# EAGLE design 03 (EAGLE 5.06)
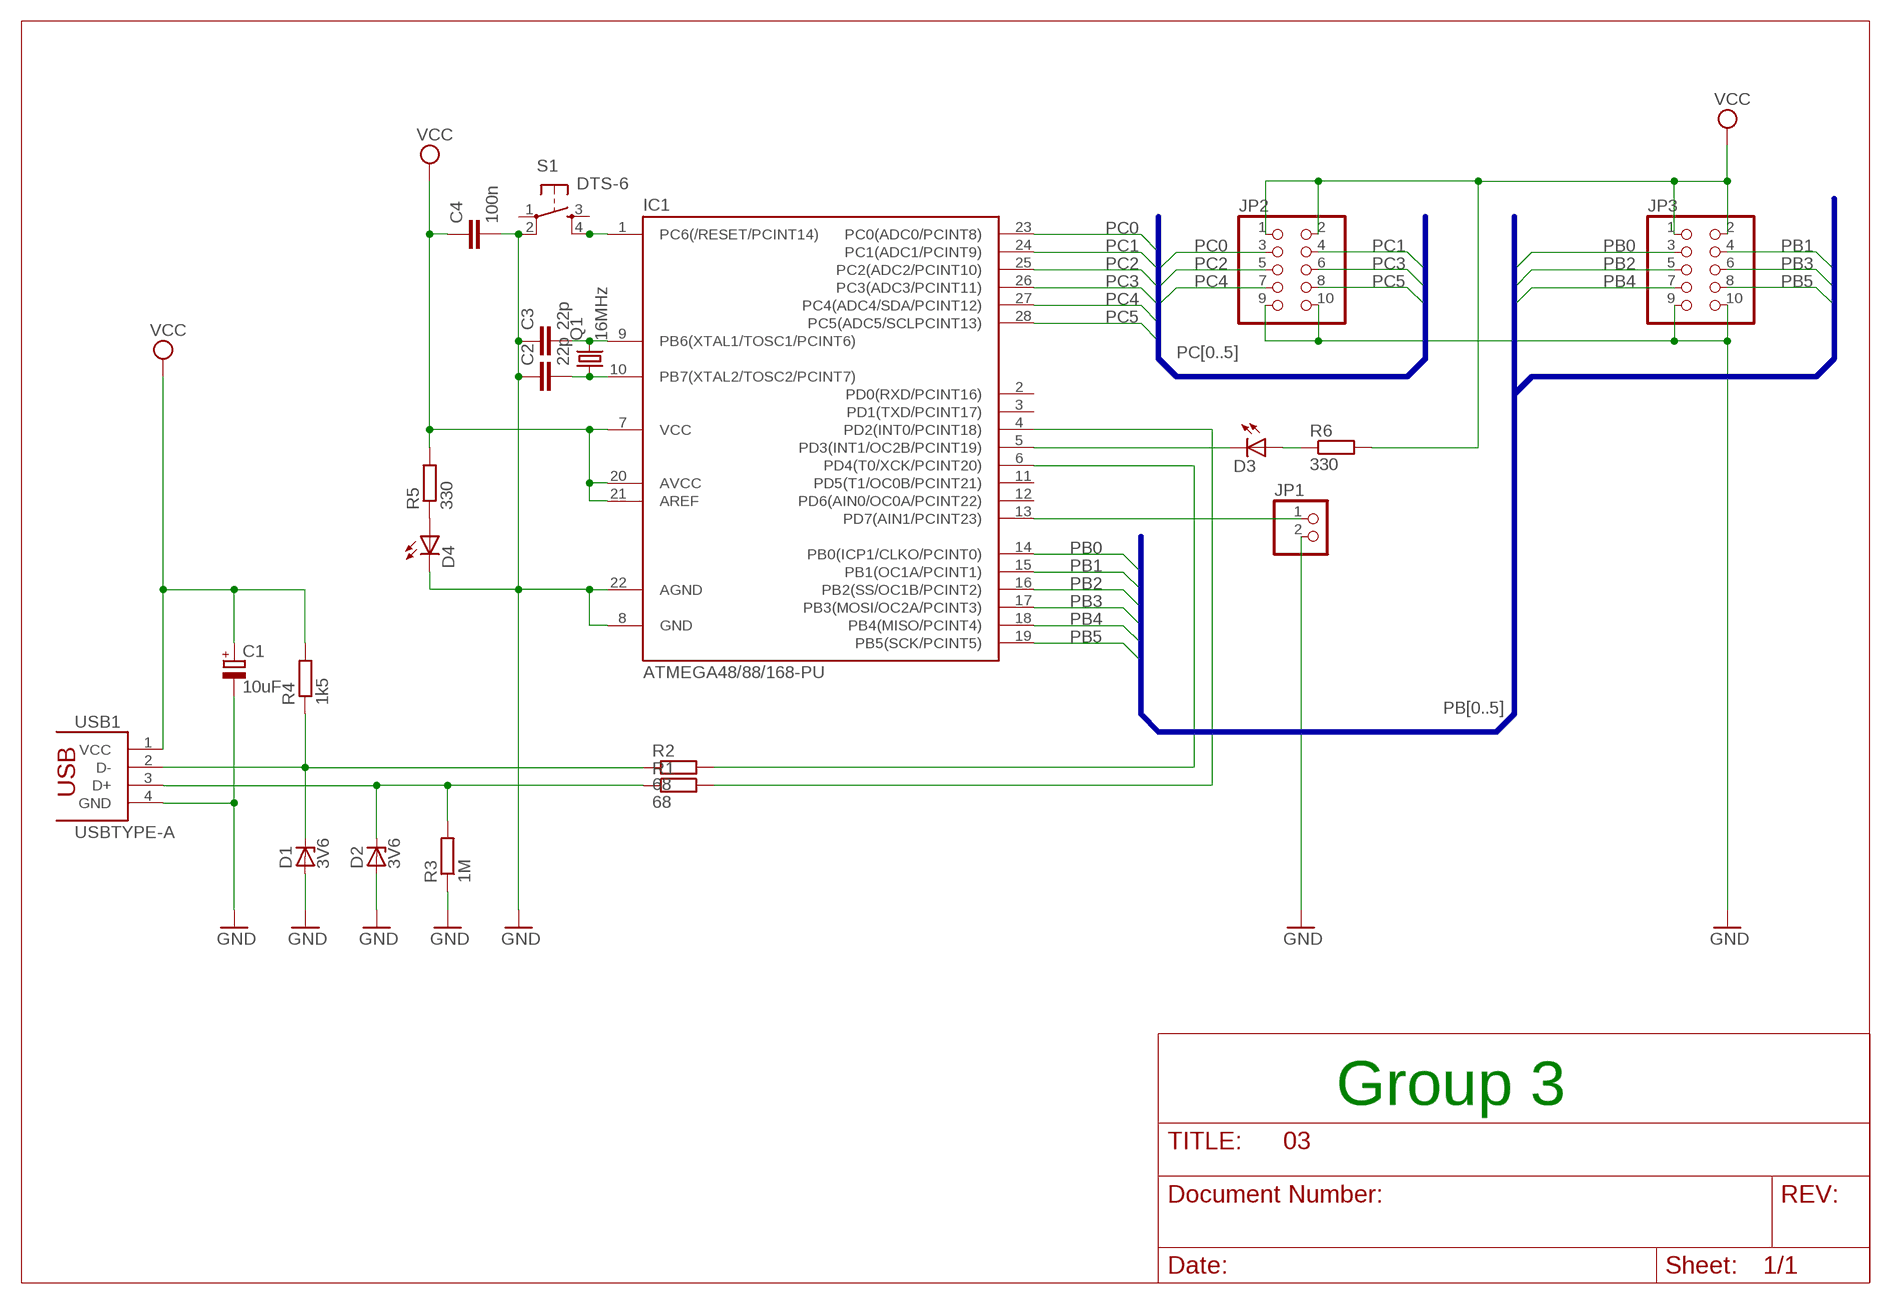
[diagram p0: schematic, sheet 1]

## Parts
C1  10uF  CPOL-EUE2,5-6E  [E2,5-6E]
C2  22p  C-EU025-024X044  [C025-024X044]
C3  22p  C-EU025-024X044  [C025-024X044]
C4  100n  C-EU050-024X044  [C050-024X044]
D1  3V6  ZENER-DIODEDO34-7  [DO34Z7]
D2  3V6  ZENER-DIODEDO34-7  [DO34Z7]
D3  LED3MM  [LED3MM]
D4  LED3MM  [LED3MM]
IC1  ATMEGA48/88/168-PU  [DIL28-3]
JP1  PINHD-1X2  [1X02]
JP2  PINHD-2X5  [2X05]
JP3  PINHD-2X5  [2X05]
Q1  16MHz  CRYSTALHC49S  [HC49/S]
R1  68  R-EU_0207/10  [0207/10]
R2  68  R-EU_0207/10  [0207/10]
R3  1M  R-EU_0207/10  [0207/10]
R4  1k5  R-EU_0207/10  [0207/10]
R5  330  R-EU_0207/10  [0207/10]
R6  330  R-EU_0207/10  [0207/10]
S1  DTS-6  [DTS-6]
USB1  USBTYPE-A  [USBTYPE-A]

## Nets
GND: C1.- C2.1 C3.1 C4.2 D1.A D2.A D4.K(C) IC1.8(GND) IC1.22(AGND) JP1.2 JP2.9 JP2.10 JP3.9 JP3.10 R3.1 S1.2 USB1.4(GND)
N$1: IC1.4(PD2(INT0/PCINT18)) R1.2
N$2: D4.A R5.1
N$3: D2.C R1.1 R3.2 USB1.3(D+)
N$4: D1.C R2.1 R4.1 USB1.2(D-)
N$5: IC1.1(PC6(/RESET/PCINT14)) S1.4
N$6: IC1.6(PD4(T0/XCK/PCINT20)) R2.2
N$7: D3.K(C) IC1.5(PD3(INT1/OC2B/PCINT19))
N$8: D3.A R6.1
N$9: C3.2 IC1.9(PB6(XTAL1/TOSC1/PCINT6)) Q1.2
N$10: C2.2 IC1.10(PB7(XTAL2/TOSC2/PCINT7)) Q1.1
N$11: IC1.13(PD7(AIN1/PCINT23)) JP1.1
PB0: IC1.14(PB0(ICP1/CLKO/PCINT0)) JP3.3
PB1: IC1.15(PB1(OC1A/PCINT1)) JP3.4
PB2: IC1.16(PB2(SS/OC1B/PCINT2)) JP3.5
PB3: IC1.17(PB3(MOSI/OC2A/PCINT3)) JP3.6
PB4: IC1.18(PB4(MISO/PCINT4)) JP3.7
PB5: IC1.19(PB5(SCK/PCINT5)) JP3.8
PC0: IC1.23(PC0(ADC0/PCINT8)) JP2.3
PC1: IC1.24(PC1(ADC1/PCINT9)) JP2.4
PC2: IC1.25(PC2(ADC2/PCINT10)) JP2.5
PC3: IC1.26(PC3(ADC3/PCINT11)) JP2.6
PC4: IC1.27(PC4(ADC4/SDA/PCINT12)) JP2.7
PC5: IC1.28(PC5(ADC5/SCLPCINT13)) JP2.8
VCC: C1.+ C4.1 IC1.7(VCC) IC1.20(AVCC) IC1.21(AREF) JP2.1 JP2.2 JP3.1 JP3.2 R4.2 R5.2 R6.2 USB1.1(VCC)
Unconnected: IC1.2(PD0(RXD/PCINT16)) IC1.3(PD1(TXD/PCINT17)) IC1.11(PD5(T1/OC0B/PCINT21)) IC1.12(PD6(AIN0/OC0A/PCINT22)) S1.1 S1.3

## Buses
PC[0..5]
PB[0..5]

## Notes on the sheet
- Group 3

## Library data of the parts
C1 = rcl:CPOL-EU: POLARIZED CAPACITOR, European symbol
C2-C4 = rcl:C-EU: CAPACITOR, European symbol
D1 D2 = diode:ZENER-DIODE: Z-Diode
D3 D4 = led:LED: LED
IC1 = atmega8:ATMEGA48/88/168-PU
JP1 = pinhead:PINHD-1X2: PIN HEADER
JP2 JP3 = pinhead:PINHD-2X5: PIN HEADER
Q1 = crystal:CRYSTAL: CRYSTAL
R1-R6 = rcl:R-EU_: RESISTOR, European symbol
S1 = switch-tact:DTS-6
USB1 = USBTYPE-A:USBTYPE-A

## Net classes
0 default: width 0.406 mm

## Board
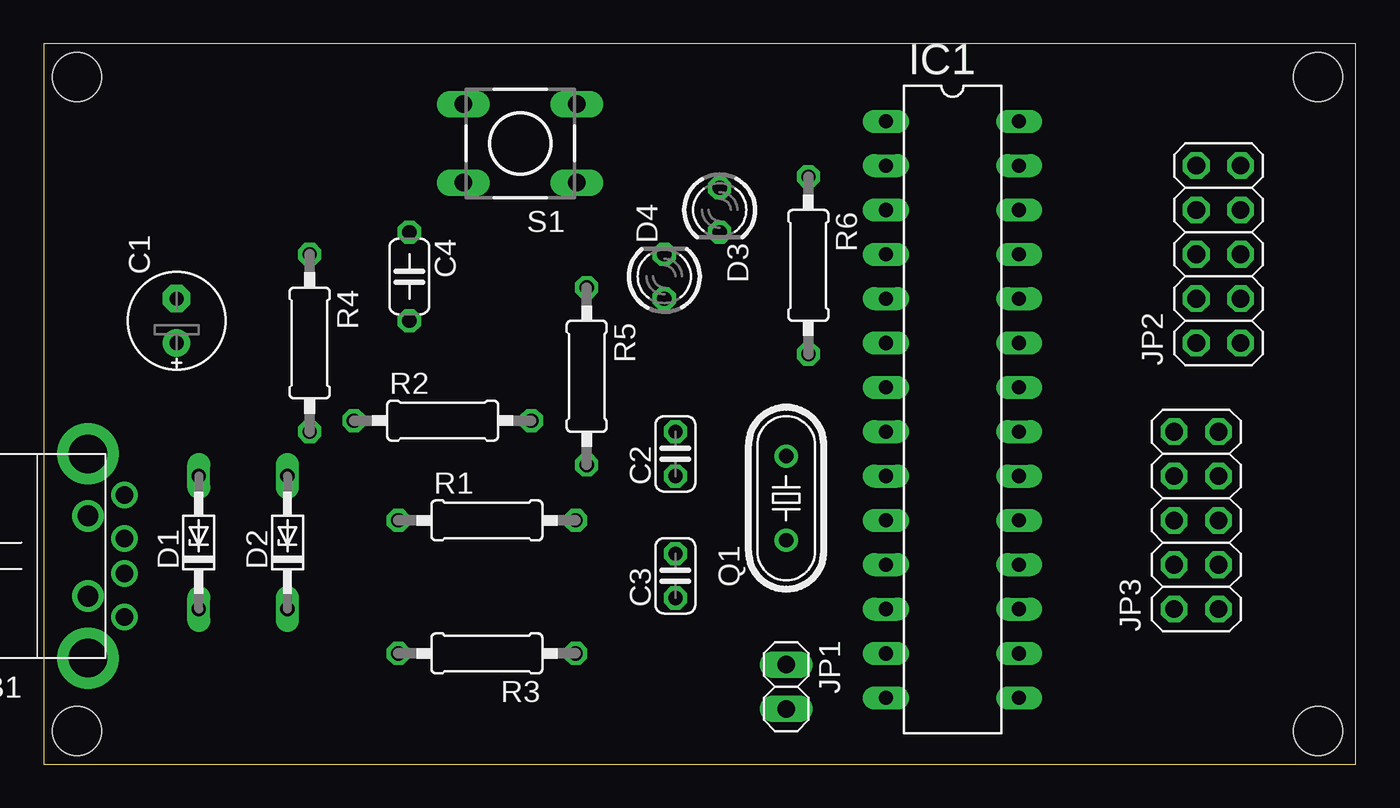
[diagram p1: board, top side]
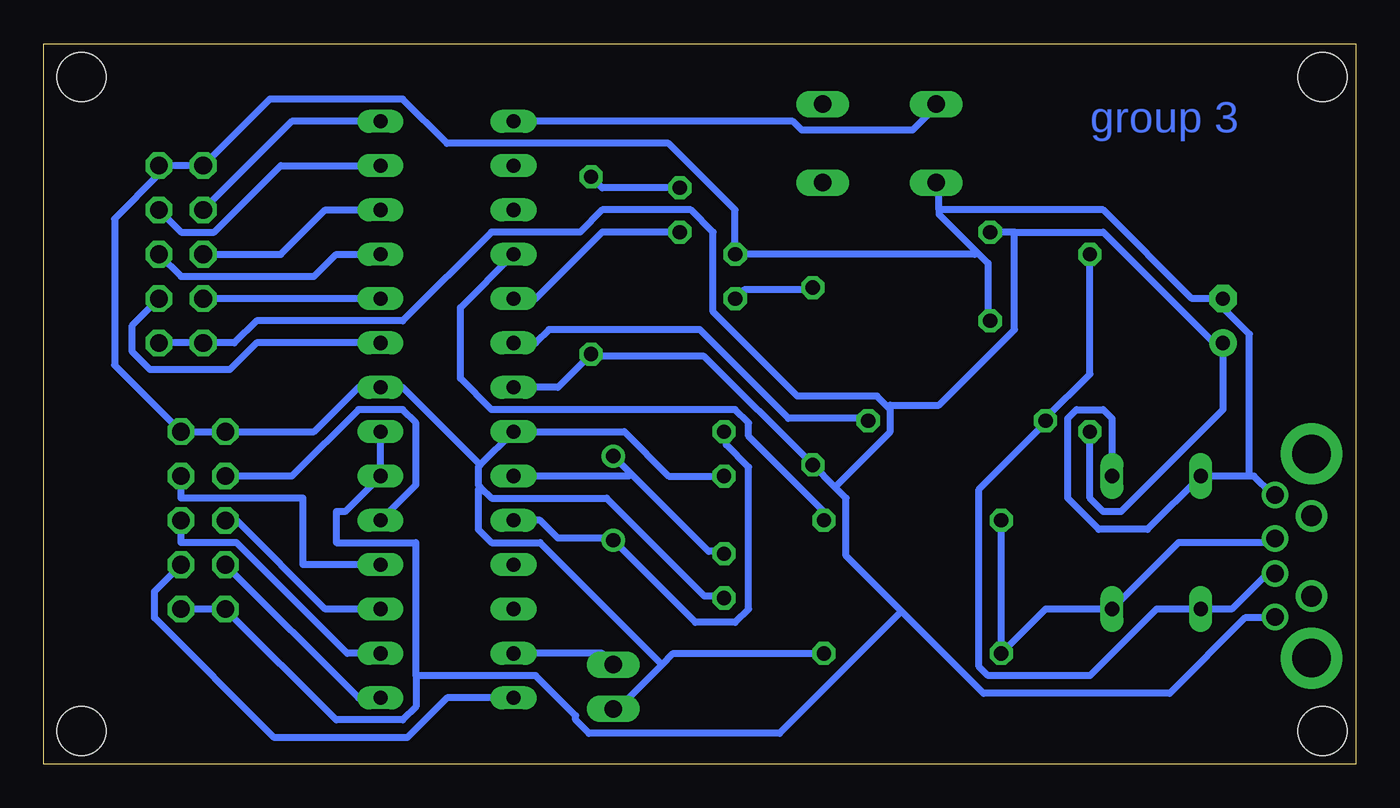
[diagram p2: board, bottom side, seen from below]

Size 75.18 x 41.27 mm. Coordinates in mm from the lower left corner, seen from the top.
Outline: 0,41.27 0,0 75.18,0 75.18,41.27 0,41.27
Copper layers (1*16): Top 0.035mm / dielectric 1.5mm / Bottom 0.035mm
Design rules "default *": minimum track width 10mil, minimum drill 24mil, track to track 8mil, track to pad 8mil, pad to pad 8mil, via to via 8mil, smd to smd 8mil, copper to edge 40mil, drill to drill 8mil, minimum pad ring 10mil, minimum via ring 8mil, stop-mask expansion 4mil, vias tented up to drill 0mil, thermal gap 10mil
Holes 2.8 mm at 1.91,1.91 73.03,1.91 73.03,39.37 1.91,39.37

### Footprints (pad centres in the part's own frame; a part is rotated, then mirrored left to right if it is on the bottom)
E2,5-6E = drill 0.813 pad 1.575 round: + -1.27,0 | drill 0.813 pad 1.575 octagon: - 1.27,0
C025-024X044 = drill 0.813 octagon: 1 -1.27,0; 2 1.27,0
C050-024X044 = drill 0.813 octagon: 1 -2.54,0; 2 2.54,0
DO34Z7 = drill 0.813 long: A 3.81,0; C -3.81,0
LED3MM = drill 0.813 octagon: A -1.27,0; K 1.27,0
DIL28-3 = drill 0.813 long: 1 -16.51,-3.81; 2 -13.97,-3.81; 3 -11.43,-3.81; 4 -8.89,-3.81; 5 -6.35,-3.81; 6 -3.81,-3.81; 7 -1.27,-3.81; 8 1.27,-3.81; 9 3.81,-3.81; 10 6.35,-3.81; 11 8.89,-3.81; 12 11.43,-3.81; 13 13.97,-3.81; 14 16.51,-3.81; 15 16.51,3.81; 16 13.97,3.81; 17 11.43,3.81; 18 8.89,3.81; 19 6.35,3.81; 20 3.81,3.81; 21 1.27,3.81; 22 -1.27,3.81; 23 -3.81,3.81; 24 -6.35,3.81; 25 -8.89,3.81; 26 -11.43,3.81; 27 -13.97,3.81; 28 -16.51,3.81
1X02 = drill 1.016 long: 1 -1.27,0; 2 1.27,0
2X05 = drill 1.016 octagon: 1 -5.08,-1.27; 2 -5.08,1.27; 3 -2.54,-1.27; 4 -2.54,1.27; 5 0,-1.27; 6 0,1.27; 7 2.54,-1.27; 8 2.54,1.27; 9 5.08,-1.27; 10 5.08,1.27
HC49/S = drill 0.813 round: 1 -2.413,0; 2 2.413,0
0207/10 = drill 0.813 octagon: 1 -5.08,0; 2 5.08,0
DTS-6 = drill 1 long: 1 -3.25,2.25; 2 3.25,2.25; 3 -3.25,-2.25; 4 3.25,-2.25
USBTYPE-A = drill 1 round: 1 -2.1,9.35; 2 -2.1,6.85; 3 -2.1,4.85; 4 -2.1,2.35 | drill 2.2 pad 3.5 round: GND@1 0,0; GND@2 0,11.7 | drill 1.2 pad 1.6 round: S1 0,3.55; S2 0,8.15

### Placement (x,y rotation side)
C1  7.62,25.4 90 top
C2  36.2,17.78 90 top
C3  36.2,10.79 90 top
C4  20.95,27.94 270 top
D1  8.89,12.7 90 top
D2  13.97,12.7 90 top
D3  38.73,31.75 270 top
D4  35.56,27.94 90 top
IC1  52.07,20.32 270 top
JP1  42.55,4.45 270 top
JP2  67.31,29.21 90 top
JP3  66.04,13.97 90 top
Q1  42.55,15.24 90 top
R1  25.4,13.97 0 top
R2  22.86,19.68 0 top
R3  25.4,6.35 180 top
R4  15.24,24.13 270 top
R5  31.11,22.23 270 top
R6  43.81,28.57 270 top
S1  27.3,35.56 180 top
USB1  2.54,17.78 180 top

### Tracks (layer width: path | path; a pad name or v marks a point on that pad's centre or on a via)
GND
  Bottom 0.406: 6.1,16.51 5.84,16.51 4.83,15.49 USB1.4 | 6.1,16.51 D1.A 11.94,13.46 14.73,13.46 16.51,15.24 16.51,19.81 16,20.32 14.48,20.32 13.97,19.81 D2.A | 6.1,16.51 6.1,24.64 7.62,26.16 C1.- 9.4,26.67 14.48,31.75 23.88,31.75 | 21.72,29.34 23.88,31.5 23.88,31.75 | 21.72,29.34 21.08,28.7 21.08,25.4 C4.2 | 23.88,31.75 23.88,33.27 S1.2 | 21.72,29.34 21.84,29.21 D4.K 35.56,31.75 39.37,35.56 52.07,35.56 54.61,38.1 62.23,38.1 JP2.10 JP2.9 68.58,33.78 71.12,31.24 71.12,22.86 JP3.9 JP3.10 59.69,19.05 57.15,21.59 IC1.22 54.61,21.59 50.16,17.14 | R3.1 39.12,6.35 39.75,5.71 | 39.75,5.71 42.42,3.05 JP1.2 | 50.16,15.88 50.29,16 50.29,17.02 50.16,17.14 | 50.16,15.88 49.53,15.24 42.93,15.24 37.34,9.65 36.32,9.65 C3.1 | 50.16,17.14 IC1.8 41.91,19.05 39.37,16.51 C2.1 | 39.75,5.71 46.74,12.7 49.53,12.7 50.29,13.46 50.29,15.75 50.16,15.88
N$1
  Bottom 0.406: R1.2 30.48,14.48 34.8,18.8 34.8,19.56 35.56,20.32 49.53,20.32 51.31,22.1 51.31,26.16 IC1.4
N$2
  Bottom 0.406: D4.A 35.05,27.18 31.24,27.18 R5.1
N$3
  Bottom 0.406: R1.1 R3.2 17.78,8.89 D2.C 10.16,12.7 4.83,12.7 USB1.3
N$4
  Bottom 0.406: USB1.2 4.83,11.18 7.11,8.89 D1.C 11.43,8.89 15.24,5.08 21.08,5.08 21.59,5.59 21.59,15.75 17.78,19.56 R2.1 17.78,19.81 15.24,22.35 R4.1
N$5
  Bottom 0.406: IC1.1 32.26,36.83 31.75,36.32 25.4,36.32 24.13,37.59 S1.4
N$6
  Bottom 0.406: IC1.6 46.99,24.13 46.23,24.89 37.59,24.89 32.51,19.81 27.94,19.81 R2.2
N$7
  Bottom 0.406: IC1.5 46.99,26.67 43.18,30.48 D3.K
N$8
  Bottom 0.406: D3.A 43.18,33.02 R6.1
N$9
  Bottom 0.406: 41.53,16.64 37.08,12.19 36.32,12.19 C3.2 | 41.53,16.64 Q1.2 | IC1.9 41.66,16.51 41.53,16.64
N$10
  Bottom 0.406: IC1.10 46.74,13.97 45.72,12.95 42.67,12.95 Q1.1 37.85,8.13 35.56,8.13 34.8,8.89 34.8,17.02 36.07,18.29 36.07,19.05 C2.2
N$11
  Bottom 0.406: IC1.13 43.18,6.35 JP1.1
PB0
  Bottom 0.406: IC1.14 52.07,3.81 54.36,1.52 61.98,1.52 68.83,8.38 68.83,9.91 JP3.3
PB1
  Bottom 0.406: IC1.15 57.15,3.81 JP3.4
PB2
  Bottom 0.406: JP3.5 67.31,12.7 64.14,12.7 57.78,6.35 IC1.16
PB3
  Bottom 0.406: IC1.17 59.05,8.89 64.14,13.97 JP3.6
PB4
  Bottom 0.406: IC1.18 60.33,11.43 60.33,15.24 67.31,15.24 JP3.7
PB5
  Bottom 0.406: IC1.19 53.85,16 53.85,19.56 54.61,20.32 57.15,20.32 60.96,16.51 JP3.8
PC0
  Bottom 0.406: IC1.23 62.99,24.13 64.52,22.61 69.09,22.61 70.1,23.62 70.1,25.15 JP2.3
PC1
  Bottom 0.406: IC1.24 JP2.4
PC2
  Bottom 0.406: JP2.5 67.31,27.94 59.69,27.94 58.42,29.21 IC1.25
PC3
  Bottom 0.406: JP2.6 61.59,29.21 59.05,31.75 IC1.26
PC4
  Bottom 0.406: JP2.7 67.31,30.48 65.41,30.48 61.59,34.29 IC1.27
PC5
  Bottom 0.406: IC1.28 60.96,36.83 JP2.8
VCC
  Bottom 0.406: R4.2 15.24,15.24 14.48,14.48 13.46,14.48 7.62,20.32 7.62,23.62 | 19.56,30.48 14.48,30.48 7.62,23.62 | 19.56,30.48 C4.1 | 7.62,23.62 C1.+ | IC1.21 IC1.20 57.91,14.48 58.42,14.48 58.42,12.7 53.85,12.7 53.85,5.08 | JP3.1 JP3.2 58.42,2.54 54.61,2.54 53.85,3.3 53.85,5.08 | JP2.1 JP2.2 64.26,24.13 62.99,25.4 54.61,25.4 49.53,30.48 44.45,30.48 43.18,31.75 38.1,31.75 36.83,30.48 36.83,25.91 32,21.08 27.43,21.08 26.8,20.45 | IC1.7 45.72,21.59 R6.2 43.69,23.37 37.34,23.37 R5.2 29.84,15.88 | 26.04,8.76 29.21,11.94 29.21,15.24 29.84,15.88 | 26.04,8.76 21.34,4.06 10.67,4.06 6.35,8.38 4.83,8.38 USB1.1 | 26.8,20.45 26.67,20.32 26.67,19.05 29.84,15.88 | 53.85,5.08 46.99,5.08 44.7,2.79 44.7,2.54 43.94,1.78 33.02,1.78 26.04,8.76 | 19.56,30.48 19.56,24.89 23.88,20.57 26.67,20.57 26.8,20.45

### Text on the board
Bottom: group 3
